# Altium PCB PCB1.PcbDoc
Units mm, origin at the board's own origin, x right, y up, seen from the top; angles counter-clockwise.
Board outline 72.2 x 34.3 mm, 2 copper layers (Top Layer, Bottom Layer); 27 components, 15 nets, 72 pads, 39 vias.
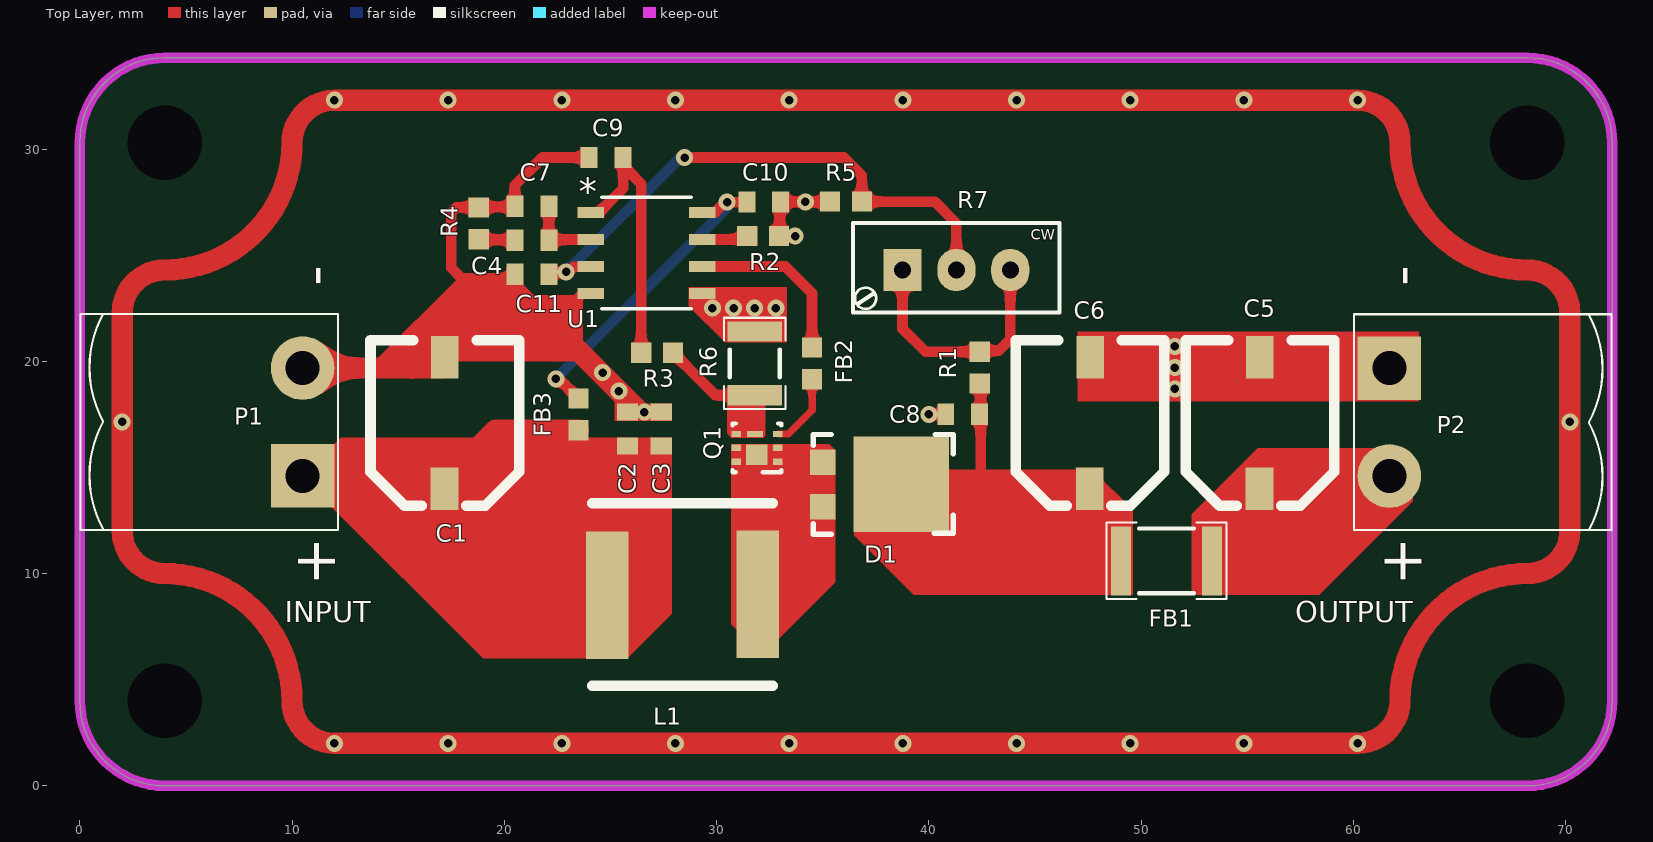
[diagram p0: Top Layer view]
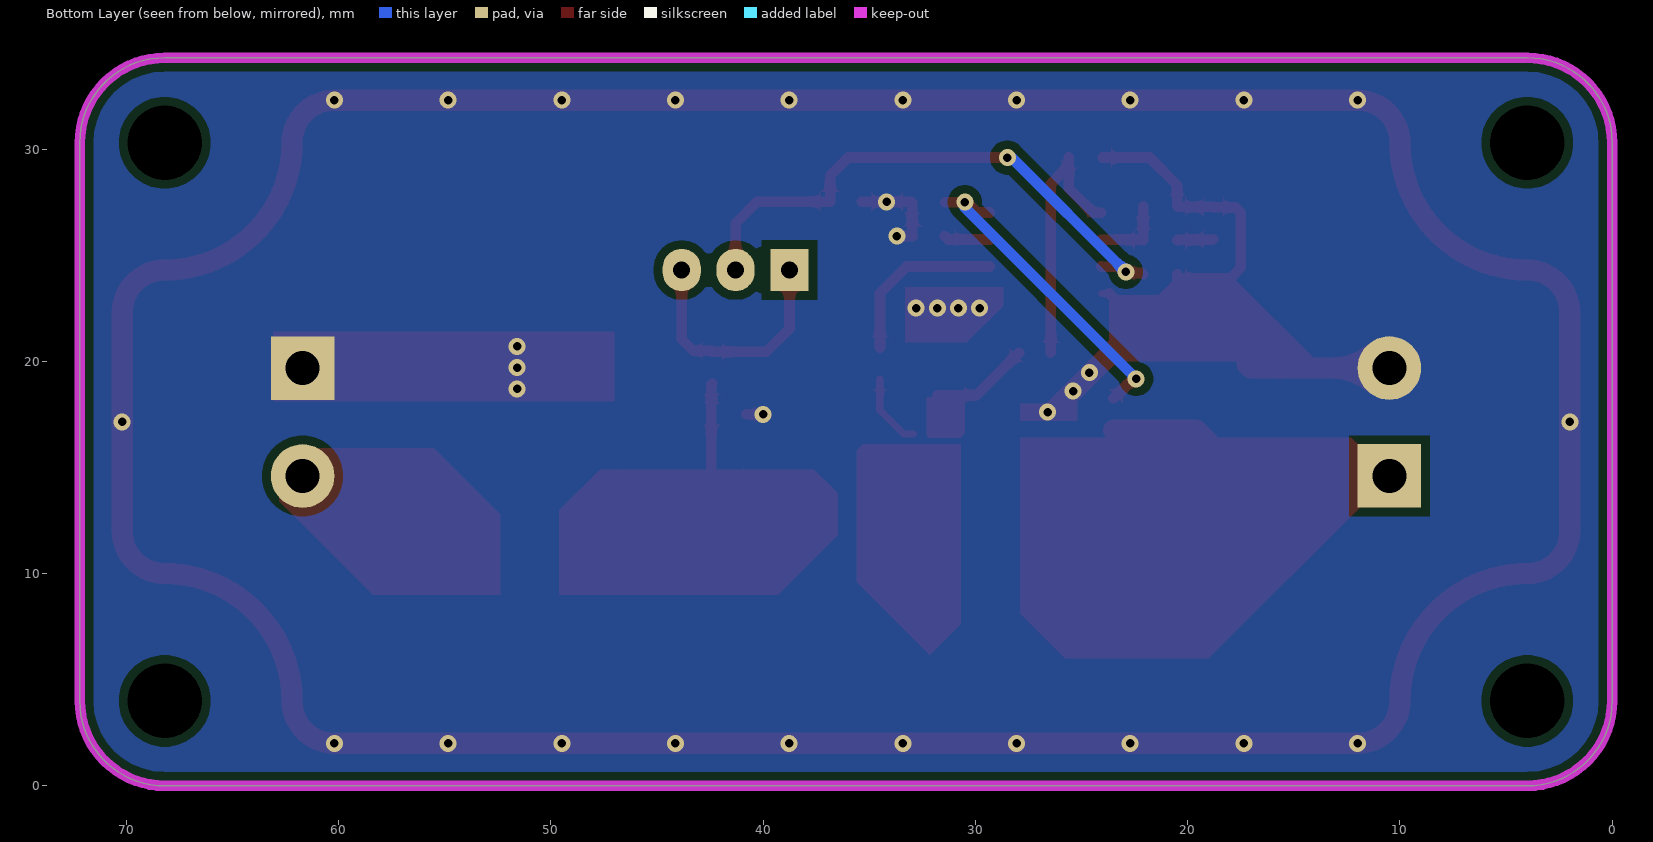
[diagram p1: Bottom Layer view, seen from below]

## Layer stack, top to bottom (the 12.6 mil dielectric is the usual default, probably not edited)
Top Solder: solder mask 0.0102, Solder Resist, Dk 3.5
Top Layer: signal copper 0.0356
Dielectric 1: dielectric 0.32, FR-4, Dk 4.8
Bottom Layer: signal copper 0.0356
Bottom Solder: solder mask 0.0102, Solder Resist, Dk 3.5

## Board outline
4,0 cw(c4,4) 0,4 0,30.3 cw(c4,30.3) 4,34.3 68.2,34.3 cw(c68.2,30.3) 72.2,30.3 72.2,4 cw(c68.2,4) 68.2,0

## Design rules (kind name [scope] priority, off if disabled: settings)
Clearance POLY [InPolygon] p1: gap=0.4 ignorepadtopadclearanceinfootprint=FALSE
Clearance [All] p2: gap=0.3 ignorepadtopadclearanceinfootprint=FALSE
Height [All] p1: minheight=0 maxheight=12 prefheight=6
MinimumAnnularRing [All] p1: minimumring=0.2
PolygonConnect [All] p1: connectstyle=Direct reliefconductorwidth=0.254 reliefentries=4 polygonreliefangle="90 Angle" airgapwidth=0.254
RoutingVias [All] p1: holewidth=0.4 width=0.8 viastyle="Through Hole" minholewidth=0.4 minwidth=0.8 maxholewidth=0.4 maxwidth=0.8
SolderMaskExpansion [All] p1: expansion=0.102 istentingtop=FALSE
Width [All] p1: maxlimit=1 minlimit=0.3 preferedwidth=0.5
29 further rules are at their usual default settings.

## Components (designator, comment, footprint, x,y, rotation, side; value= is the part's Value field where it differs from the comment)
C1 "865060343005" CAP-6.3x5.5 17.2,17.1 r90 top value=100uF
C2 "Cap" CAPC1608X08N 25.8,16.8 r90 top value=100nF
C3 "Cap" CAPC1608X08N 27.4,16.8 r90 top value=100nF
C4 "CC1206JRNPO9BN101" CAPC1608X08N 21.3,25.7 r180 top value=18nF
C5 "865060343005" CAP-6.3x5.5 55.6,17.1 r90 top value=100uF
C6 "865060343005" CAP-6.3x5.5 47.6,17.1 r90 top value=100uF
C7 "CC1206JRNPO9BN101" CAPC1608X08N 21.3,27.3 r180 top value=1nF
C8 "Cap" CAPC1608X08N 41.6,17.5 r180 top value=100nF
C9 "CC1206JRNPO9BN101" CAPC1608X08N 24.8,29.6 r180 top value=47pF
C10 "Cap" CAPC1608X08N 32.225,27.5 r180 top value=100nF
C11 "CC1206JRNPO9BN101" CAPC1608X08N 21.3,24.1 r180 top value=47pF
D1 "SS10P4-M3/86A" SS10P4 38.4,14.2 r270 top
FB1 "YI453215U101-8R0T" "RES1812 thick" 51.2,10.6 r0 top value=0.6
FB2 "BLM18HE152SN1D" RESC1608X06N 34.5,19.9 r90 top value=0.6
FB3 "BLM18HE152SN1D" RESC1608X06N 23.5,17.5 r90 top value=0.6
L1 "IHLP3232DZER5R6M11" IHLP3232DZ 28.4,9 r0 top value=5.6uH
P1 "Header 2" phonix2 10.5,14.6 r90 top
P2 "Header 2" phonix2 61.7,19.674 r270 top
Q1 "CSD17571Q2" DQK0006C 31.9,15.925 r180 top
R1 "1206W4F1002T5E" RESC1608X06N 42.4,19.7 r270 top value=8.2K
R2 "1206W4F1002T5E" RESC1608X06N 32.2,25.9 r0 top value=22K
R3 "1206W4F1002T5E" RESC1608X06N 27.2,20.4 r0 top value=100
R4 "1206W4F1002T5E" RESC1608X06N 18.8,26.5 r90 top value=4.7K
R5 "1206W4F1002T5E" RESC1608X06N 36.1,27.525 r0 top value=1.2K
R6 "FRL1210JR015TS" RES1210 31.8,19.9 r270 top value=15m
R7 "RPot" "Multi Turn" 38.76,24.3 r90 top value=5K
U1 "LM3478MA/NOPB" M08A 26.7,25.1 r0 top

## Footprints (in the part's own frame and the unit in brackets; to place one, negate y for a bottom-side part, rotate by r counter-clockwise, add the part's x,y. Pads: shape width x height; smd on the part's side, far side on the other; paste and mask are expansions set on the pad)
CAP-6.3x5.5 [mm]
  rect 2x1.3 smd: 1(-3.104,0.018) 2(3.1,0)
  silkscreen extent -3.9,-3.5 3.9,3.5, body extent -3.8,-3.4 3.8,3.4, height 5.5
CAPC1608X08N [mm] "Chip Capacitor, 2-Leads, Body 1.60x0.80mm, IPC Medium Density"
  rect 0.8x1 smd: 1(0.8,0) 2(-0.8,0)
  body extent -0.9,-0.48 0.9,0.47, height 0.85
DQK0006C [mm]
  rect 0.45x0.3 smd paste+0 mask+0.051: 1(-0.975,-0.65) 2(-0.975,0) 2(-0.975,0.65) 2(0.975,0) 2(0.975,0.65) 3(0.975,-0.65)
  rect 1x0.95 smd paste-0.487 mask+0.051: 2(0,0.325)
  rect 0.75x0.3 smd paste-0.362 mask+0.051: 3(0.095,-0.65)
  silkscreen extent -1.15,-1.15 1.15,1.15, body extent -1,-1 1,1, height 0.8
IHLP3232DZ [mm]
  rect 2x6 smd: 1(-3.548,-0.018) 2(3.548,0.018)
  silkscreen extent -4.25,-4.28 4.25,4.32, body extent -4.3,-4.08 4.3,4.12, height 3.87
M08A [mil]
  rect 49.41x20 smd paste+0 mask+0: 1(-103.2,75) 2(-103.2,25) 3(-103.2,-25) 4(-103.2,-75) 5(103.2,-75) 6(103.2,-25) 7(103.2,25) 8(103.2,75)
  silkscreen extent -84,-104 84,104, body extent -122,-99 122,99, height 69
"Multi Turn" [mm] "Multi-turn potentiometer, pitch 100mils, lead diameter 0.5mm WxHxL: 4.7x7.3x6.8mm"
  oval 2x1.8 hole 0.8: 1(0,-5.08) 2(0,-2.54)
  rect 2x1.8 hole 0.8: 3(0,0)
  silkscreen extent -2,-7.4 2.22,2.33, body extent -2.1,-7.28 2.11,2.22, height 11.49
phonix2 [mm]
  rect 3x3 hole 1.6: 1(0,0)
  round 3 hole 1.6: 2(5.08,0)
  silkscreen extent -2.54,-1.67 7.62,10.46, body extent -2.63,-1.54 7.7,10.39, height 7.88
RES1210 [mm] "Chip Resistor, 2-Leads, Body 3/20x2/50mm, IPC Medium Density DESIGNER:ABBAS BASEREH"
  rect 0.95x2.55 smd: 1(-1.5,0) 2(1.5,0)
  silkscreen extent -2.15,-1.45 2.15,1.45, body extent -1.63,-1.28 1.63,1.28, height 0.55
"RES1812 thick" [mm]
  rect 0.95x3.25 smd: 1(-2.15,0) 2(2.15,0)
  silkscreen extent -2.83,-1.8 2.83,1.8, body extent -2.25,-1.57 2.25,1.62, height 2.35
RESC1608X06N [mm] "Chip Resistor, 2-Leads, Body 1.60x0.85mm, IPC Medium Density"
  rect 0.95x0.95 smd: 1(0.75,0) 2(-0.75,0)
  body extent -0.88,-0.48 0.87,0.47, height 0.55
SS10P4 [mm]
  rect 1.2x1.2 smd: 1(-1.05,-3.4) 1(1.05,-3.4)
  rect 4.5x4.5 smd: 2(0,0.3)
  silkscreen extent -2.35,-3.85 2.35,2.75, body extent -2.3,-3.91 2.3,2.59, height 1.05

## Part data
C1 C5 C6: library part "Cap Pol1", "Aluminium Electrolytic Capacitors - SMD WCAP-ASLL 100uF 16V 20% SMD/SMT"
C2 C3 C8 C10: "Capacitor"
C4 C7 C9 C11: library part Cap, "50V 100pF NP0 ±5% 1206 Multilayer Ceramic Capacitors MLCC - SMD/SMT ROHS"
D1: library part Diode, "40V Independent 480mV@10A 10A TO-277A-3 Single Diodes ROHS"
FB1: library part Res2, "10mΩ ±25% 100Ω@100MHz 1812 Ferrite Bead"
FB2 FB3: library part Res2, "500mΩ ±25% 1.5kΩ@100MHz 0603 Ferrite Bead"
L1: library part Inductor, "5.6 µH Shielded Molded Inductor 7.4 A 28.6mOhm"
P1 P2: "Header, 2-Pin"
Q1: library part IRFP143, "30V 22A 29mΩ@4.5V,5A 2.5W 2V 1 N-Channel WSON-6(2x2) Single FETs, MOSFETs ROHS"
R1 R2 R3 R4 R5: library part Res2, "0.25W Thick Film Resistors 200V ±100ppm/℃ ±1% 10kΩ 1206 Chip Resistor - Surface Mount ROHS"
R6: library part Res2, "500mW 15mΩ Thick Film Resistor ±5% 1210 Chip Resistor - Surface Mount ROHS"
R7: "Potentiometer"
U1: library part LM3478MANOPB, "2.97~40V Wide Input Range Boost/SEPIC/Flyback DC-DC Controller 8-SOIC -40 to 125", Manufacturer_Name="Texas Instruments"

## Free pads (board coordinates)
  round 0 hole 3.5: 2(4,4) 2(4,30.3) 2(68.2,4) 2(68.2,30.3)

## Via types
v1: diameter 0.8, hole 0.4, Top Layer to Bottom Layer, 22 vias
v2: diameter 0.8, hole 0.4, Top Layer to Bottom Layer, tented both sides, 17 vias

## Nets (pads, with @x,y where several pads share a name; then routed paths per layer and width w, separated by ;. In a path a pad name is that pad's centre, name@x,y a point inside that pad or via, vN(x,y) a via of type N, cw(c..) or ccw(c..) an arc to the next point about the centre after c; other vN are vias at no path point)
+12: C5.1 FB1.2 P2.2 | length 5.6
  Top Layer w1: C5.1@56.144,14.594 P2.2
FB: C11.2 R5.1 R7.2 U1.3 | length 27
  Top Layer w0.5: C11.2 22.16,24.16 22.859,24.16 22.919,24.1 22.919,24.136 23.057,24.275 23.093,24.275 23.28,24.461 24.075,24.461 U1.3 ; v2(28.5,29.6) 36,29.6 36.85,28.75 R5.1 40.275,27.525 41.3,26.5 R7.2
  Bottom Layer w0.5: v2(22.919,24.217) 28.301,29.6 v2(28.5,29.6)
GND: C1.2 C2.1 C3.1 C5.2 C6.2 C7.1 C8.1 C9.1 C10.2 C11.1 P1.2 P2.1 R2.1 R4.1 R5.2 R6.1 U1.4 U1.5 | length 246.4
  Top Layer w0.3: C11.1@20.3,23.9 C11.1 ; U1.4@23.705,23.195 U1.4
  Top Layer w0.5: C11.1@20.3,23.9 18,23.9 17.5,24.4 17.5,27 17.75,27.25 R4.1 18.825,27.275 20.475,27.275 C7.1 20.5,28.3 21.8,29.6 C9.1 ; C11.1 20.5,23.9 20.5,23.5 ; U1.4@23.705,23.195 23.31,22.8 20.5,22.8 20.5,23.5 ; C3.1 C2.1 25.67,17.73 25.67,18.43 23.6,20.5 17.5,20.5 C1.2 17.2,20.55 17.6,20.95 17.95,20.95 20.5,23.5 ; U1.5 29.325,23.191 30.309,23.191 31.168,22.332 31.168,21.625 31.575,21.625 R6.1 ; C10.2@33,27.5 32.975,27.475 32.975,25.925 R2.1 v2(33.7,25.9) ; C10.2 33.038,27.512 v2(34.188,27.512) 35.338,27.512 R5.2 ; v2(40,17.5) C8.1
  Top Layer w1: P1.2 17.03,19.68 17.2,19.85 C1.2 ; C6.2 C5.2 55.6,20.087 55.75,19.937 61.437,19.937 P2.1 ; 2,12 ccw(c4,12) 4,10 cw(c4,4) 10,4 ccw(c12,4) v1(12,2) v1(60.2,2) ccw(c60.2,4) 62.2,4 cw(c68.2,4) 68.2,10 ccw(c68.2,12) 70.2,12 70.2,22.3 ccw(c68.2,22.3) 68.2,24.3 cw(c68.2,30.3) 62.2,30.3 ccw(c60.2,30.3) v1(60.2,32.3) v1(12,32.3) ccw(c12,30.3) 10,30.3 cw(c4,30.3) 4,24.3 ccw(c4,22.3) 2,22.3 2,12
  other v1: 17.356,2 22.711,2 28.067,2 33.422,2 38.778,2 44.133,2 49.489,2 54.844,2 2,17.15 70.2,17.15 17.356,32.3 22.711,32.3 28.067,32.3 33.422,32.3 38.778,32.3 44.133,32.3 49.489,32.3 54.844,32.3
  other v2: 26.6,17.6 25.4,18.6 51.6,18.7 24.635,19.465 51.6,19.7 51.6,20.7 29.8,22.5 30.8,22.5 31.8,22.5 32.8,22.5
Isen: C9.2 R3.2 U1.1 | length 12.6
  Top Layer w0.5: U1.1 24.452,27.005 25.6,28.153 C9.2@25.6,29.2 ; C9.2 C9.2@25.6,29.2 ; R3.2 26.45,28.35 C9.2@25.6,29.2
NetC4_1: C4.1 R4.2 | length 1.7
  Top Layer w0.5: R4.2 18.825,25.725 20.475,25.725 C4.1
NetC4_2: C4.2 C7.2 U1.2 | length 3.6
  Top Layer w0.5: C7.2 C4.2 22.131,25.731 24.075,25.731 U1.2
NetC6_1: C6.1 C8.2 D1.2 FB1.1 R1.1 | length 14.7
  Top Layer w0.5: R1.1 42.45,18.9 42.45,14.25 42.5,14.2
  Top Layer w1: D1.2 38.904,13.996 C6.1 47.732,13.846 C6.1@47.732,13.118
NetC10_1: C10.1 FB3.1 U1.8 | length 15.2
  Top Layer w0.5: v2(22.429,19.171) 22.486,19.114 22.636,19.114 FB3.1 ; U1.8 29.325,27.009 29.909,27.009 v2@30.337,27.437 ; v2(30.5,27.5) C10.1
  Bottom Layer w0.5: v2(22.429,19.171) 30.5,27.243 v2(30.5,27.5)
NetD1_1: D1.1 L1.2 Q1.2 | length 8.7
  Top Layer w0.5: D1.1@35,13.15 D1.1@35,15.25
  Top Layer w1: Q1.2@31.9,15.6 31.948,15.552 L1.2
NetFB2_1: FB2.1 U1.6 | length 8.3
  Top Layer w0.5: U1.6 33.235,24.465 34.5,23.2 FB2.1
NetFB2_2: FB2.2 Q1.1 | length 3.5
  Top Layer w0.35: Q1.1@32.925,16.575 33.375,16.575 34.5,17.7 FB2.2
NetQ1_3: Q1.3 R3.1 R6.2 | length 5.6
  Top Layer w0.3: Q1.3@30.925,16.575 31.58,16.575 Q1.3@31.805,16.575
  Top Layer w0.5: R3.1 29.95,18.4 R6.2
NetR1_2: R1.2 R7.1 R7.3 | length 11.8
  Top Layer w0.5: R7.3 38.76,21.54 39.85,20.45 R1.2 42.45,20.5 43.3,20.5 43.84,21.04 R7.1
NetR2_2: R2.2 U1.7 | length 2.2
  Top Layer w0.5: U1.7 29.325,25.739 31.289,25.739 R2.2
VCC: C1.1 C2.2 C3.2 FB3.2 L1.1 P1.1 | length 24.4
  Top Layer w1: P1.1 16.929,14.6 C1.1@17.182,14.346 ; FB3.2 19.586,16.75 C1.1@17.182,14.346 ; L1.1 24.434,9.4 21.429,9.4 17.182,13.646 C1.1 C1.1@17.182,14.346

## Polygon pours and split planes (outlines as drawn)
GND on Bottom Layer "GND_L2" (solid, pour order 0): 0.3,34.3 72.2,34.3 72.2,0 0.3,0

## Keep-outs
Keep-Out Layer:
  lines w0.5: 0,30.2 0,4 ccw(c4,4) 4,0 68.2,0 ccw(c68.2,4) 72.2,4 72.2,30.3 ccw(c68.2,30.3) 68.2,34.3 4.1,34.3 ; 0,30.3 cw(c4,30.3) 4,34.3

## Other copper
Top Layer:
  region net GND: 63.1,21.4 47,21.4 47,18.1 63.1,18.1
  region net GND: 25.2,17.2 25.2,18.1 23.3,20 13.9,20 17.8,23.9 20.6,23.9 21.4,23.1 23.5,23.1 23.7,22.9 23.7,21 26.7,18 27.9,18 27.9,17.2
  region net +12: 52.4,9 58.4,9 62.8,13.4 62.8,15.3 62.2,15.9 55.5,15.9 52.4,12.8
  region net NetC6_1: 37.6,14.9 36.5,13.8 36.5,11.8 39.3,9 49.6,9 49.6,13 47.7,14.9
  region net GND: 30.4,20.9 28.7,22.6 28.7,23.5 33.3,23.5 33.3,20.9
  region net NetQ1_3: 32.2,16.4 32.3,16.5 32.3,18.3 30.5,18.3 30.5,16.6 30.7,16.4
  region net VCC: 27.9,16.4 12.3,16.4 11.5,15.6 11.5,13.5 19,6 25.8,6 27.9,8.1
  region net NetD1_1: 30.7,16.1 30.7,7.6 32.15,6.15 35.6,9.6 35.6,15.8 35.3,16.1

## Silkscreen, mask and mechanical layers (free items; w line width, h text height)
Top Overlay:
  text "-" at 12,23.534 h2 r90
  text "-" at 63.2,23.528 h2 r90
  text "+" at 12.033,9.434 h2 r90
  text "+" at 63.233,9.428 h2 r90
  text "INPUT" at 9.651,7.7 h1
  text "OUTPUT" at 57.268,7.7 h1
Top Solder:
  lines w1: 2,12 ccw(c4,12) 4,10 cw(c4,4) 10,4 ccw(c12,4) 12,2 60.2,2 ccw(c60.2,4) 62.2,4 cw(c68.2,4) 68.2,10 ccw(c68.2,12) 70.2,12 70.2,22.3 ccw(c68.2,22.3) 68.2,24.3 cw(c68.2,30.3) 62.2,30.3 ccw(c60.2,30.3) 60.2,32.3 12,32.3 ccw(c12,30.3) 10,30.3 cw(c4,30.3) 4,24.3 ccw(c4,22.3) 2,22.3 2,12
